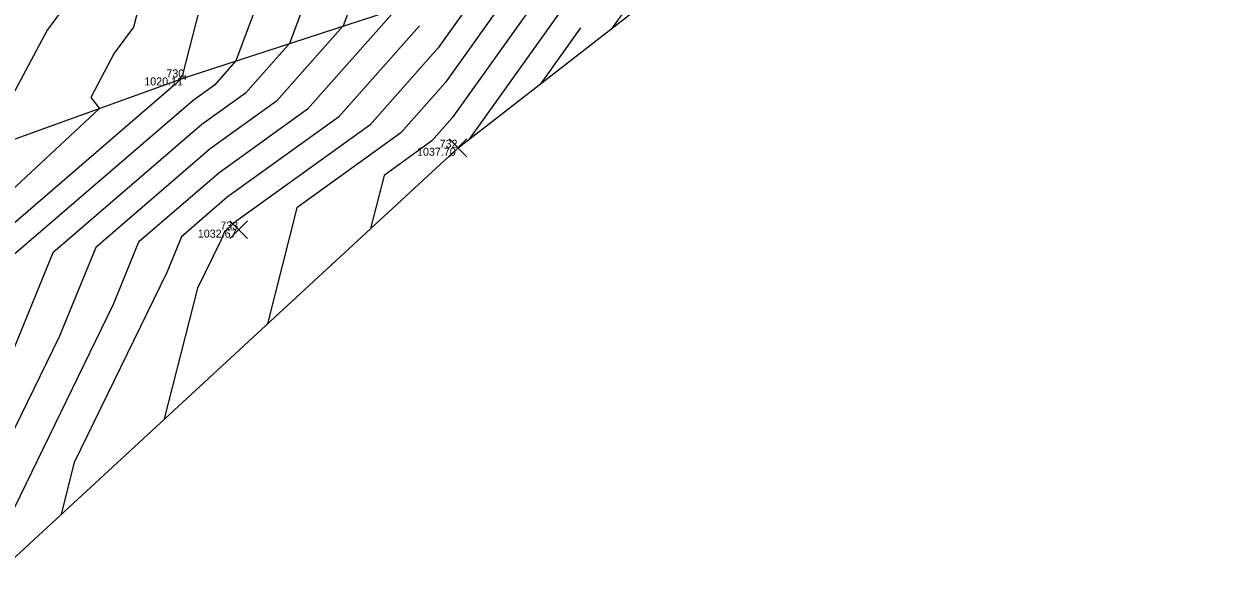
# Model space of a CAD drawing. Extents: x 2354693 to 2355622, y 637071 to 710080.
# Drawn here: x 2355430.4 to 2355608.2, y 709131.5 to 709213 of the extents above; entities that cross this region are included whole.
import ezdxf

# ---------------------------------------------------------------- set-up
doc = ezdxf.new("R2010")
doc.units = 0
for name, color, linetype in [('Default', 7, 'Continuous'), ('DT_X_Contour_Major', 7, 'Continuous'), ('DT_X_Contour_Minor', 7, 'Continuous'), ('SV_X_Random_Point', 7, 'Continuous'), ('SV_X_Shot_Marker', 7, 'Continuous'), ('SV_X_Text_Elevation', 7, 'Continuous'), ('SV_X_Text_Name', 7, 'Continuous'), ('SV_X_Toe_of_Slope', 7, 'Continuous')]:
    doc.layers.add(name, color=color, linetype=linetype)

msp = doc.modelspace()

# ---------------------------------------------------------------- linework, layer by layer
at = {"layer": 'Default'}
msp.add_lwpolyline([(2355263.76, 708986.4), (2355330.91, 709003.61), (2355347.35, 709002.09), (2355387.45, 709051.54), (2355402.1, 709089.16), (2355425.96, 709130.16), (2355495.56, 709194.41), (2355530.33, 709221.46), (2355525, 709302.12), (2355509.66, 709318.33), (2355534.8, 709413.26), (2355566.11, 709428.47), (2355585.74, 709473.78), (2355589.64, 709532.44), (2355608.23, 709591.27)], dxfattribs=at)
msp.add_lwpolyline([(2355263.76, 708986.4), (2355330.91, 709003.61), (2355347.35, 709002.09), (2355387.45, 709051.54), (2355402.1, 709089.16), (2355425.96, 709130.16), (2355495.56, 709194.41), (2355530.33, 709221.46), (2355525, 709302.12), (2355509.66, 709318.33), (2355534.8, 709413.26), (2355566.11, 709428.47), (2355585.74, 709473.78), (2355589.64, 709532.44), (2355608.23, 709591.27)], dxfattribs=at)
at = {"layer": 'DT_X_Contour_Major'}
for points in [[(2355456.69, 709227.11), (2355457.48, 709226.2), (2355459.26, 709225.12), (2355454.22, 709205.33), (2355454.08, 709205.14), (2355453.9, 709204.8), (2355453.96, 709204.72), (2355452.92, 709203.76), (2355421.91, 709177.07), (2355419.27, 709170.6), (2355416.05, 709165.77), (2355412.7, 709160.36), (2355405.68, 709150.4), (2355404.68, 709148.79)], [(2355456.69, 709227.11), (2355457.48, 709226.2), (2355459.26, 709225.12), (2355454.22, 709205.33), (2355454.08, 709205.14), (2355453.9, 709204.8), (2355453.96, 709204.72), (2355452.92, 709203.76), (2355421.91, 709177.07), (2355419.27, 709170.6), (2355416.05, 709165.77), (2355412.7, 709160.36), (2355405.68, 709150.4), (2355404.68, 709148.79)], [(2355489.75, 709212.69), (2355477.64, 709199.02), (2355460.94, 709186.98), (2355454.07, 709181.06), (2355451.88, 709175.7), (2355437.98, 709147.19), (2355436.02, 709139.45)], [(2355489.75, 709212.69), (2355477.64, 709199.02), (2355460.94, 709186.98), (2355454.07, 709181.06), (2355451.88, 709175.7), (2355437.98, 709147.19), (2355436.02, 709139.45)], [(2355513.9, 709212.39), (2355507.97, 709204.06)], [(2355513.9, 709212.39), (2355507.97, 709204.06)]]:
    msp.add_lwpolyline(points, dxfattribs=at)
at = {"layer": 'DT_X_Contour_Minor'}
for points in [[(2355510.91, 709323.07), (2355509.87, 709321.98), (2355508.68, 709319.47), (2355507.43, 709317), (2355493.75, 709298.08), (2355489, 709291.97), (2355477.54, 709271.27), (2355473.88, 709270.13), (2355468.81, 709269.95), (2355462.23, 709258.3), (2355443.4, 709243.24), (2355441.47, 709241.59), (2355440.08, 709236.93), (2355439.04, 709229.6), (2355438.39, 709227.08), (2355441.03, 709225.48), (2355439.54, 709219.65), (2355433.91, 709212.05), (2355427.03, 709199.09)], [(2355510.91, 709323.07), (2355509.87, 709321.98), (2355508.68, 709319.47), (2355507.43, 709317), (2355493.75, 709298.08), (2355489, 709291.97), (2355477.54, 709271.27), (2355473.88, 709270.13), (2355468.81, 709269.95), (2355462.23, 709258.3), (2355443.4, 709243.24), (2355441.47, 709241.59), (2355440.08, 709236.93), (2355439.04, 709229.6), (2355438.39, 709227.08), (2355441.03, 709225.48), (2355439.54, 709219.65), (2355433.91, 709212.05), (2355427.03, 709199.09)], [(2355512.06, 709315.8), (2355511, 709314.24), (2355498.24, 709296.58), (2355491.64, 709288.12), (2355475.75, 709259.39), (2355474.35, 709258.95), (2355467.42, 709258.71), (2355465.44, 709255.21), (2355459.78, 709250.68), (2355449.72, 709242.03), (2355446.52, 709231.3), (2355446.05, 709228.22), (2355446.84, 709227.3), (2355450.15, 709225.3), (2355446.88, 709212.49), (2355443.99, 709208.59), (2355440.46, 709201.95), (2355441.77, 709200.32), (2355421.1, 709181.12)], [(2355512.06, 709315.8), (2355511, 709314.24), (2355498.24, 709296.58), (2355491.64, 709288.12), (2355475.75, 709259.39), (2355474.35, 709258.95), (2355467.42, 709258.71), (2355465.44, 709255.21), (2355459.78, 709250.68), (2355449.72, 709242.03), (2355446.52, 709231.3), (2355446.05, 709228.22), (2355446.84, 709227.3), (2355450.15, 709225.3), (2355446.88, 709212.49), (2355443.99, 709208.59), (2355440.46, 709201.95), (2355441.77, 709200.32), (2355421.1, 709181.12)], [(2355518.27, 709309.23), (2355514.46, 709303.63), (2355507.21, 709293.59), (2355496.93, 709280.4), (2355484.12, 709257.23), (2355477.7, 709247.29), (2355474.77, 709240.12), (2355466.09, 709240.88), (2355464.34, 709229.47), (2355468.12, 709225.09), (2355468.38, 709224.93), (2355467.59, 709221.81), (2355462.23, 709207.44), (2355459.02, 709203.82), (2355455.82, 709201.52), (2355428.34, 709177.87)], [(2355518.27, 709309.23), (2355514.46, 709303.63), (2355507.21, 709293.59), (2355496.93, 709280.4), (2355484.12, 709257.23), (2355477.7, 709247.29), (2355474.77, 709240.12), (2355466.09, 709240.88), (2355464.34, 709229.47), (2355468.12, 709225.09), (2355468.38, 709224.93), (2355467.59, 709221.81), (2355462.23, 709207.44), (2355459.02, 709203.82), (2355455.82, 709201.52), (2355428.34, 709177.87)], [(2355521.38, 709305.94), (2355516.2, 709298.32), (2355511.7, 709292.09), (2355499.57, 709276.54), (2355491.01, 709261.05), (2355479.93, 709243.88), (2355474.87, 709231.51), (2355473.72, 709231.61), (2355473.49, 709230.09), (2355474.12, 709229.36), (2355473.63, 709226.98), (2355476.06, 709226.81), (2355475.08, 709222.95), (2355470.27, 709210.06), (2355463.67, 709202.62), (2355457.1, 709197.88), (2355434.77, 709178.67), (2355427.81, 709161.59)], [(2355521.38, 709305.94), (2355516.2, 709298.32), (2355511.7, 709292.09), (2355499.57, 709276.54), (2355491.01, 709261.05), (2355479.93, 709243.88), (2355474.87, 709231.51), (2355473.72, 709231.61), (2355473.49, 709230.09), (2355474.12, 709229.36), (2355473.63, 709226.98), (2355476.06, 709226.81), (2355475.08, 709222.95), (2355470.27, 709210.06), (2355463.67, 709202.62), (2355457.1, 709197.88), (2355434.77, 709178.67), (2355427.81, 709161.59)], [(2355524.49, 709302.66), (2355517.93, 709293.02), (2355516.18, 709290.6), (2355502.22, 709272.68), (2355497.89, 709264.86), (2355482.16, 709240.47), (2355478.46, 709231.43), (2355478.07, 709229.49), (2355483.44, 709229.13), (2355481.26, 709220.6), (2355478.31, 709212.69), (2355468.33, 709201.42), (2355458.38, 709194.25), (2355441.2, 709179.47), (2355435.74, 709166.06), (2355427.13, 709148.41)], [(2355524.49, 709302.66), (2355517.93, 709293.02), (2355516.18, 709290.6), (2355502.22, 709272.68), (2355497.89, 709264.86), (2355482.16, 709240.47), (2355478.46, 709231.43), (2355478.07, 709229.49), (2355483.44, 709229.13), (2355481.26, 709220.6), (2355478.31, 709212.69), (2355468.33, 709201.42), (2355458.38, 709194.25), (2355441.2, 709179.47), (2355435.74, 709166.06), (2355427.13, 709148.41)], [(2355525.5, 709294.55), (2355524.58, 709290.12), (2355519.34, 709284.91), (2355519.01, 709285.31), (2355518.76, 709286.73), (2355505.62, 709269.79), (2355504.86, 709268.82), (2355504.78, 709268.67), (2355484.39, 709237.07), (2355482.68, 709232.9), (2355482.5, 709232.01), (2355490.82, 709231.44), (2355487.45, 709218.24), (2355486.35, 709215.31), (2355472.99, 709200.22), (2355459.66, 709190.62), (2355447.63, 709180.27), (2355443.81, 709170.88), (2355426.26, 709134.89)], [(2355525.5, 709294.55), (2355524.58, 709290.12), (2355519.34, 709284.91), (2355519.01, 709285.31), (2355518.76, 709286.73), (2355505.62, 709269.79), (2355504.86, 709268.82), (2355504.78, 709268.67), (2355484.39, 709237.07), (2355482.68, 709232.9), (2355482.5, 709232.01), (2355490.82, 709231.44), (2355487.45, 709218.24), (2355486.35, 709215.31), (2355472.99, 709200.22), (2355459.66, 709190.62), (2355447.63, 709180.27), (2355443.81, 709170.88), (2355426.26, 709134.89)], [(2355526.7, 709276.45), (2355523.56, 709261.43), (2355521.06, 709258.93), (2355518.89, 709261.52), (2355517.25, 709270.73), (2355508.68, 709259.68), (2355493.77, 709236.98), (2355498.97, 709236.52), (2355505.58, 709236.08), (2355503.3, 709227.15), (2355504.8, 709224.78), (2355498.48, 709217.72), (2355492.57, 709209.42), (2355482.3, 709197.82), (2355462.22, 709183.35), (2355460.5, 709181.86), (2355459.95, 709180.52), (2355456.46, 709173.36), (2355451.49, 709153.73)], [(2355526.7, 709276.45), (2355523.56, 709261.43), (2355521.06, 709258.93), (2355518.89, 709261.52), (2355517.25, 709270.73), (2355508.68, 709259.68), (2355493.77, 709236.98), (2355498.97, 709236.52), (2355505.58, 709236.08), (2355503.3, 709227.15), (2355504.8, 709224.78), (2355498.48, 709217.72), (2355492.57, 709209.42), (2355482.3, 709197.82), (2355462.22, 709183.35), (2355460.5, 709181.86), (2355459.95, 709180.52), (2355456.46, 709173.36), (2355451.49, 709153.73)], [(2355527.3, 709267.4), (2355523.06, 709247.09), (2355521.92, 709245.95), (2355518.83, 709249.63), (2355516.5, 709262.74), (2355510.59, 709255.11), (2355500.29, 709239.44), (2355510.04, 709238.59), (2355512.96, 709238.39), (2355511.95, 709234.45), (2355514.51, 709230.4), (2355503.73, 709218.34), (2355493.62, 709204.15), (2355486.95, 709196.63), (2355471.36, 709185.38), (2355466.97, 709168.02)], [(2355527.3, 709267.4), (2355523.06, 709247.09), (2355521.92, 709245.95), (2355518.83, 709249.63), (2355516.5, 709262.74), (2355510.59, 709255.11), (2355500.29, 709239.44), (2355510.04, 709238.59), (2355512.96, 709238.39), (2355511.95, 709234.45), (2355514.51, 709230.4), (2355503.73, 709218.34), (2355493.62, 709204.15), (2355486.95, 709196.63), (2355471.36, 709185.38), (2355466.97, 709168.02)], [(2355527.89, 709258.35), (2355522.93, 709234.57), (2355508.97, 709218.95), (2355494.67, 709198.88), (2355491.61, 709195.43), (2355484.45, 709190.27), (2355482.44, 709182.3)], [(2355527.89, 709258.35), (2355522.93, 709234.57), (2355508.97, 709218.95), (2355494.67, 709198.88), (2355491.61, 709195.43), (2355484.45, 709190.27), (2355482.44, 709182.3)], [(2355528.49, 709249.3), (2355524.75, 709231.35), (2355514.21, 709219.57), (2355497.2, 709195.68)], [(2355528.49, 709249.3), (2355524.75, 709231.35), (2355514.21, 709219.57), (2355497.2, 709195.68)], [(2355529.69, 709231.2), (2355528.38, 709224.92), (2355524.69, 709220.8), (2355518.74, 709212.44)], [(2355529.69, 709231.2), (2355528.38, 709224.92), (2355524.69, 709220.8), (2355518.74, 709212.44)]]:
    msp.add_lwpolyline(points, dxfattribs=at)
at = {"layer": 'SV_X_Random_Point'}
for p, q in [((2355494.22, 709193.07), (2355496.89, 709195.74)), ((2355494.22, 709195.74), (2355496.89, 709193.07)), ((2355461.32, 709180.8), (2355463.99, 709183.47)), ((2355461.32, 709183.47), (2355463.99, 709180.8))]:
    msp.add_line(p, q, dxfattribs=at)
at = {"layer": 'SV_X_Shot_Marker'}
for p, q in [((2355454.61, 709205.26), (2355454.61, 709204.66)), ((2355454.91, 709204.96), (2355454.31, 709204.96))]:
    msp.add_line(p, q, dxfattribs=at)
at = {"layer": 'SV_X_Toe_of_Slope'}
msp.add_lwpolyline([(2355330.91, 709003.61), (2355357.29, 709054.66), (2355376.63, 709104.12), (2355386.68, 709149.19), (2355392.84, 709167.31), (2355399.71, 709185.13), (2355454.61, 709204.96), (2355491.09, 709216.85), (2355522.63, 709235.09)], dxfattribs=at)

# ---------------------------------------------------------------- texts
at = {"layer": 'SV_X_Text_Elevation'}
for s, p in [('1020.11', (2355448.49, 709203.76)), ('1037.70', (2355489.4, 709193.21)), ('1032.67', (2355456.52, 709180.93))]:
    msp.add_text(s, height=1.2, dxfattribs=at).set_placement(p)
at = {"layer": 'SV_X_Text_Name'}
for s, p in [('730', (2355451.8, 709204.96)), ('732', (2355492.79, 709194.41)), ('733', (2355459.89, 709182.13))]:
    msp.add_text(s, height=1.2, dxfattribs=at).set_placement(p)

doc.saveas('drawing.dxf')
